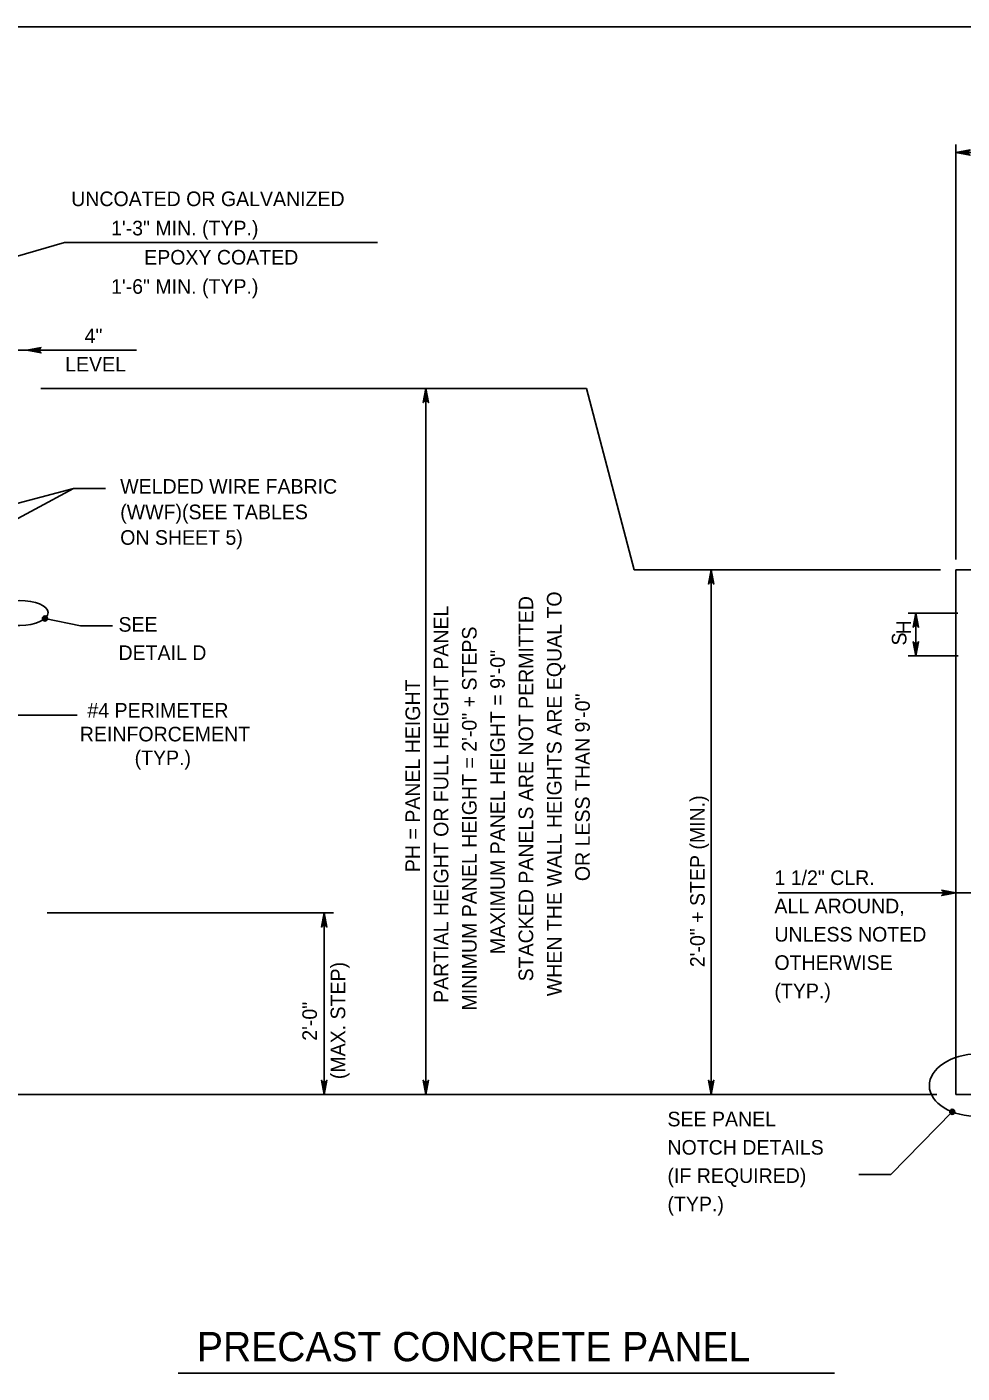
# Model space of a CAD drawing. Extents: x 3761 to 5458, y -616 to 1166.
# Drawn here: x 4899.2 to 5095.9, y -320.4 to -37.3 of the extents above; entities that cross this region are included whole.
import ezdxf

# ---------------------------------------------------------------- set-up
doc = ezdxf.new("R2010")
doc.units = 0
doc.layers.add('1', color=7, linetype='Continuous')
doc.layers.add('2', color=7, linetype='Continuous')

msp = doc.modelspace()

# ---------------------------------------------------------------- linework, layer by layer
at = {"layer": '1'}
for p, q in [((5094.63, -149.35), (5094.63, -62.05)), ((5094.63, -63.74), (5237.13, -63.74)), ((4907.09, -82.64), (4871.93, -92.92)), ((4972.96, -82.64), (4907.09, -82.64)), ((4888.31, -105.32), (4922.25, -105.32)), ((4902.16, -113.34), (5016.9, -113.34)), ((4983.14, -261.84), (4983.14, -113.34)), ((5026.96, -151.51), (5016.9, -113.34)), ((4909.02, -134.37), (4863.95, -146.42)), ((4909.02, -134.37), (4877.13, -151.59)), ((4909.02, -134.37), (4915.76, -134.37)), ((5026.96, -151.51), (5091.37, -151.51)), ((5043.14, -261.84), (5043.14, -151.51)), ((5094.63, -151.51), (5094.63, -261.84)), ((5094.63, -151.51), (5237.13, -151.51)), ((5084.6, -160.59), (5095.04, -160.59)), ((5086.24, -169.59), (5086.24, -160.59)), ((4910.47, -163.25), (4902.99, -161.73)), ((4910.47, -163.25), (4917.21, -163.25)), ((5084.6, -169.59), (5095.13, -169.59)), ((4909.76, -182.07), (4894.71, -182.07)), ((5105.15, -219.44), (5057.23, -219.44)), ((4903.44, -223.67), (4963.68, -223.67)), ((4961.75, -261.84), (4961.75, -223.67)), ((4791.48, -261.84), (5090.62, -261.84)), ((5124.84, -261.84), (5094.63, -261.84)), ((5080.96, -278.7), (5093.86, -265.5)), ((5074.22, -278.7), (5080.96, -278.7)), ((4931.01, -320.44), (5069.11, -320.44))]:
    msp.add_line(p, q, dxfattribs=at)
for points in [[(5094.63, -63.74), (5097.61, -63.18), (5097.38, -63.34), (5097.26, -63.54), (5097.23, -63.74), (5097.26, -63.94), (5097.38, -64.14), (5097.61, -64.3), (5094.63, -63.74), (5097.38, -64.14), (5097.26, -63.94), (5094.63, -63.74), (5097.23, -63.74), (5097.26, -63.54), (5094.63, -63.74), (5097.38, -63.34)], [(4899.21, -105.32), (4902.19, -104.76), (4901.96, -104.92), (4901.84, -105.12), (4901.81, -105.32), (4901.84, -105.52), (4901.96, -105.72), (4902.19, -105.88), (4899.21, -105.32), (4901.96, -105.72), (4901.84, -105.52), (4899.21, -105.32), (4901.81, -105.32), (4901.84, -105.12), (4899.21, -105.32), (4901.96, -104.92)], [(4983.14, -113.34), (4983.7, -116.32), (4983.62, -116.21), (4983.54, -116.09), (4983.44, -116.03), (4983.34, -115.97), (4983.24, -115.96), (4983.14, -115.94), (4983.04, -115.96), (4982.94, -115.97), (4982.84, -116.03), (4982.74, -116.09), (4982.66, -116.21), (4982.58, -116.32), (4983.14, -113.34), (4982.66, -116.21), (4982.74, -116.09), (4983.14, -113.34), (4982.84, -116.03), (4982.94, -115.97), (4983.14, -113.34), (4983.04, -115.96), (4983.14, -115.94), (4983.14, -113.34), (4983.24, -115.96), (4983.34, -115.97), (4983.14, -113.34), (4983.44, -116.03), (4983.54, -116.09), (4983.14, -113.34), (4983.62, -116.21)], [(5043.14, -151.51), (5043.7, -154.49), (5043.54, -154.26), (5043.34, -154.15), (5043.14, -154.11), (5042.94, -154.15), (5042.74, -154.26), (5042.58, -154.49), (5043.14, -151.51), (5042.74, -154.26), (5042.94, -154.15), (5043.14, -151.51), (5043.14, -154.11), (5043.34, -154.15), (5043.14, -151.51), (5043.54, -154.26)], [(5086.24, -160.59), (5086.8, -163.57), (5086.64, -163.34), (5086.44, -163.22), (5086.24, -163.19), (5086.04, -163.22), (5085.84, -163.34), (5085.68, -163.57), (5086.24, -160.59), (5085.84, -163.34), (5086.04, -163.22), (5086.24, -160.59), (5086.24, -163.19), (5086.44, -163.22), (5086.24, -160.59), (5086.64, -163.34)], [(5086.24, -169.59), (5085.68, -166.61), (5085.84, -166.84), (5086.04, -166.95), (5086.24, -166.99), (5086.44, -166.95), (5086.64, -166.84), (5086.8, -166.61), (5086.24, -169.59), (5086.64, -166.84), (5086.44, -166.95), (5086.24, -169.59), (5086.24, -166.99), (5086.04, -166.95), (5086.24, -169.59), (5085.84, -166.84)], [(5086.24, -169.59), (5085.68, -166.61), (5085.84, -166.84), (5086.04, -166.95), (5086.24, -166.99), (5086.44, -166.95), (5086.64, -166.84), (5086.8, -166.61), (5086.24, -169.59), (5086.64, -166.84), (5086.44, -166.95), (5086.24, -169.59), (5086.24, -166.99), (5086.04, -166.95), (5086.24, -169.59), (5085.84, -166.84)], [(5094.63, -219.44), (5091.65, -218.88), (5091.76, -218.96), (5091.88, -219.04), (5091.94, -219.14), (5092, -219.24), (5092.01, -219.34), (5092.03, -219.44), (5092.01, -219.54), (5092, -219.64), (5091.94, -219.74), (5091.88, -219.84), (5091.76, -219.92), (5091.65, -220), (5094.63, -219.44), (5091.76, -219.92), (5091.88, -219.84), (5094.63, -219.44), (5091.94, -219.74), (5092, -219.64), (5094.63, -219.44), (5092.01, -219.54), (5092.03, -219.44), (5094.63, -219.44), (5092.01, -219.34), (5092, -219.24), (5094.63, -219.44), (5091.94, -219.14), (5091.88, -219.04), (5094.63, -219.44), (5091.76, -218.96)], [(4961.75, -223.67), (4962.31, -226.65), (4962.15, -226.42), (4961.95, -226.3), (4961.75, -226.27), (4961.55, -226.3), (4961.35, -226.42), (4961.19, -226.65), (4961.75, -223.67), (4961.35, -226.42), (4961.55, -226.3), (4961.75, -223.67), (4961.75, -226.27), (4961.95, -226.3), (4961.75, -223.67), (4962.15, -226.42)], [(4961.75, -261.84), (4961.19, -258.86), (4961.35, -259.09), (4961.55, -259.2), (4961.75, -259.24), (4961.95, -259.2), (4962.15, -259.09), (4962.31, -258.86), (4961.75, -261.84), (4962.15, -259.09), (4961.95, -259.2), (4961.75, -261.84), (4961.75, -259.24), (4961.55, -259.2), (4961.75, -261.84), (4961.35, -259.09)], [(4983.14, -261.84), (4982.58, -258.86), (4982.66, -258.97), (4982.74, -259.09), (4982.84, -259.15), (4982.94, -259.2), (4983.04, -259.22), (4983.14, -259.24), (4983.24, -259.22), (4983.34, -259.2), (4983.44, -259.15), (4983.54, -259.09), (4983.62, -258.97), (4983.7, -258.86), (4983.14, -261.84), (4983.62, -258.97), (4983.54, -259.09), (4983.14, -261.84), (4983.44, -259.15), (4983.34, -259.2), (4983.14, -261.84), (4983.24, -259.22), (4983.14, -259.24), (4983.14, -261.84), (4983.04, -259.22), (4982.94, -259.2), (4983.14, -261.84), (4982.84, -259.15), (4982.74, -259.09), (4983.14, -261.84), (4982.66, -258.97)], [(5043.14, -261.84), (5042.58, -258.86), (5042.66, -258.97), (5042.74, -259.09), (5042.84, -259.15), (5042.94, -259.2), (5043.04, -259.22), (5043.14, -259.24), (5043.24, -259.22), (5043.34, -259.2), (5043.44, -259.15), (5043.54, -259.09), (5043.62, -258.97), (5043.7, -258.86), (5043.14, -261.84), (5043.62, -258.97), (5043.54, -259.09), (5043.14, -261.84), (5043.44, -259.15), (5043.34, -259.2), (5043.14, -261.84), (5043.24, -259.22), (5043.14, -259.24), (5043.14, -261.84), (5043.04, -259.22), (5042.94, -259.2), (5043.14, -261.84), (5042.84, -259.15), (5042.74, -259.09), (5043.14, -261.84), (5042.66, -258.97)]]:
    msp.add_lwpolyline(points, dxfattribs=at)
for centre, radius in [((4902.99, -161.73), 0.533), ((4902.99, -161.73), 0.267), ((5093.86, -265.5), 0.533), ((5093.86, -265.5), 0.267)]:
    msp.add_circle(centre, radius, dxfattribs=at)
for centre, major_axis, ratio in [((4897.71, -160.59), (-5.94, -0.09), 0.443512), ((5099.35, -259.88), (-10.3, -0.16), 0.638969)]:
    msp.add_ellipse(centre, major_axis=major_axis, ratio=ratio, dxfattribs=at)
at = {"layer": '2'}
msp.add_line((4642.34, -37.31), (5428.34, -37.31), dxfattribs=at)

# ---------------------------------------------------------------- texts
at = {"layer": '1'}
for s, height, p in [('UNCOATED OR GALVANIZED', 3.072, (4908.52, -75)), ('1\'-3" MIN. (TYP.)', 3.072, (4916.91, -81.15)), ('EPOXY COATED', 3.072, (4923.88, -87.29)), ('1\'-6" MIN. (TYP.)', 3.072, (4916.91, -93.44)), ('4"', 3.072, (4911.35, -103.82)), ('LEVEL', 3.072, (4907.25, -109.78)), ('WELDED WIRE FABRIC', 3.072, (4918.83, -135.48)), ('(WWF)(SEE TABLES', 3.072, (4918.83, -140.85)), ('ON SHEET 5)', 3.072, (4918.83, -146.23)), ('SEE', 3.072, (4918.47, -164.51)), ('DETAIL D', 3.072, (4918.47, -170.46)), ('#4 PERIMETER', 3.072, (4911.93, -182.58)), ('REINFORCEMENT', 3.072, (4910.33, -187.58)), ('(TYP.) ', 3.072, (4921.86, -192.57)), ('1 1/2" CLR.', 3.072, (5056.46, -217.78)), ('ALL AROUND,', 3.072, (5056.46, -223.74)), ('UNLESS NOTED', 3.072, (5056.46, -229.69)), ('OTHERWISE', 3.072, (5056.46, -235.64)), ('(TYP.)', 3.072, (5056.46, -241.59)), ('SEE PANEL', 3.072, (5033.96, -268.55)), ('NOTCH DETAILS', 3.072, (5033.96, -274.5)), ('(IF REQUIRED)', 3.072, (5033.96, -280.45)), ('(TYP.)', 3.072, (5033.96, -286.41)), ('PRECAST CONCRETE PANEL', 6.144, (4934.97, -317.95))]:
    msp.add_text(s, height=height, dxfattribs=at).set_placement(p)
for s, height, p in [('STACKED PANELS ARE NOT PERMITTED', 3.072, (5005.71, -238.05)), ('WHEN THE WALL HEIGHTS ARE EQUAL TO', 3.072, (5011.67, -241.18)), ('PARTIAL HEIGHT OR FULL HEIGHT PANEL', 3.072, (4987.86, -242.58)), ('MINIMUM PANEL HEIGHT = 2\'-0" + STEPS', 3.072, (4993.81, -244.19)), ('H', 3.07, (5085.19, -165.08)), ('S', 3.07, (5084.23, -167.41)), ('MAXIMUM PANEL HEIGHT = 9\'-0"', 3.072, (4999.76, -232.33)), ('PH = PANEL HEIGHT', 3.072, (4981.91, -215.08)), ('OR LESS THAN 9\'-0"', 3.072, (5017.62, -216.97)), ('2\'-0" + STEP (MIN.)', 3.072, (5041.8, -235.07)), ('(MAX. STEP)', 3.072, (4966.17, -258.62)), ('2\'-0"', 3.072, (4960.22, -250.54))]:
    msp.add_text(s, height=height, rotation=90, dxfattribs=at).set_placement(p)

doc.saveas('drawing.dxf')
